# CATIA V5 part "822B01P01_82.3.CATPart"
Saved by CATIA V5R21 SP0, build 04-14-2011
Part number: 822B01P01_82.3
Bounding box of the stored display mesh (mm): x -17.1 to 17.1, y -41.15 to 41.15, z -11.6 to 4.4
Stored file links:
  C:\Users\ALI OZGUN\Desktop\alhan\TESLIMEDILEN3\822B01P01_82.3.CATPart
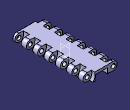
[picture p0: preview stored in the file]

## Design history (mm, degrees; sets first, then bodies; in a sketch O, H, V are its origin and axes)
Body1 (main body)
  Sketch1 on zx-plane, origin (0, 0, 0), H (-1, 0, 0), V (0, 0, 1)
    construction line L1 (-12.7, 0) -> (12.7, 0)
    point P1 (-12.7, 0)
    line L2 (-12.7, 4.4) -> (12.7, 4.4)
    line L3 (12.7, -4.4) -> (-12.7, -4.4)
    arc A1 centre (12.7, 0) radius 4.4 from (12.7, 4.4) to (12.7, -4.4) cw
    arc A2 centre (-12.7, 0) radius 4.4 from (-12.7, -4.4) to (-12.7, 4.4) cw
    distance L1 L2 = 4.4
    length L1 = 25.4
    distance P1 V = 12.7
    coincidence: P1 H
    horizontal: L1 H
    tangency: A1 L2, A2 L2, A1 L3, A2 L3
  Pad1: profile Sketch1, direction (0, 1, 0), length 76.2, mirrored extent
  Sketch2 on face of Pad1 from Sketch1.L2, origin (0, 0, 4.4), H (1, 0, 0), V (0, 1, 0)
    line L1 (-22.3127, -63.5) -> (-9.75, -63.5)
    line L2 (-9.75, -63.5) -> (-9.75, -70.6)
    line L3 (-9.75, -70.6) -> (-22.3127, -70.6)
    line L4 (-22.3127, -70.6) -> (-22.3127, -63.5)
    line L5 (24.6678, -76.95) -> (9.75, -76.95)
    line L6 (9.75, -76.95) -> (9.75, -69.85)
    line L7 (9.75, -69.85) -> (24.6678, -69.85)
    line L8 (24.6678, -69.85) -> (24.6678, -76.95)
    reference projected line E1 (-12.7, -76.2) -> (12.7, -76.2) from edge [start face of Pad1 | face of Pad1 from Sketch1.L2]
    reference projected line E2 (-12.7, -76.2) -> (12.7, -76.2) from edge [start face of Pad1 | face of Pad1 from Sketch1.L2]
    distance L3 E1 = 5.6
    length L4 = 7.1
    distance L7 L5 = 7.1
    distance L5 E2 = 0.75
    distance L2 L6 = 19.5
    distance L2 V = 9.75
    horizontal: L1 H, L3 H, L5 H, L7 H
    vertical: L2 V, L4 V, L6 V, L8 V
  Pocket1: profile Sketch2, direction (0, 0, -1), length 76.2
  RectPattern1: of Pocket1, direction 1 instances 12, spacing 12.7, along axis of face of Pad1 from Sketch1.A2
  Sketch3 on face of Pad1 from Sketch1.L3, origin (0, 0, -4.4), H (1, 0, 0), V (0, -1, 0)
    line L1 (-6.5, -54.6) -> (6.5, -54.6)
    line L2 (6.5, -54.6) -> (6.5, -73.7)
    line L3 (6.5, -73.7) -> (-6.5, -73.7)
    line L4 (-6.5, -73.7) -> (-6.5, -54.6)
    construction line L5 (-4.5, -51.1) -> (4.5, -51.1)
    point P5 (-4.5, -51.1)
    line L6 (-4.5, -49.6) -> (4.5, -49.6)
    line L7 (4.5, -52.6) -> (-4.5, -52.6)
    arc A1 centre (4.5, -51.1) radius 1.5 from (4.5, -49.6) to (4.5, -52.6) cw
    arc A2 centre (-4.5, -51.1) radius 1.5 from (-4.5, -52.6) to (-4.5, -49.6) cw
    reference projected line E1 (12.7, -76.2) -> (-12.7, -76.2) from edge [face of Pad1 from Sketch1.L3 | end face of Pad1]
    distance L5 L6 = 1.5
    distance L1 L3 = 19.1
    distance L4 L2 = 13
    distance L4 V = 6.5
    distance E1 L3 = 2.5
    distance P5 V = 4.5
    length L5 = 9
    distance L7 L1 = 2
    horizontal: L1 H, L3 H, L5 H
    vertical: L2 V, L4 V
    tangency: A1 L6, A2 L6, A1 L7, A2 L7
  Pocket2: profile Sketch3, direction (0, 0, 1), length 6
  RectPattern2: of Pocket2, direction 1 instances 6, spacing 25.8, along axis of face of Pad1 from Sketch1.A2 reversed
  Sketch4 on zx-plane, origin (0, 0, 0), H (-1, 0, 0), V (0, 0, 1)
    circle A1 centre (12.7, 0) radius 2.3
    point P1 (12.7, 0)
    circle A2 centre (-12.7, 0) radius 2.3
    point P2 (-12.7, 0)
    reference projected arc E1 centre (12.7, 0) radius 4.4 from (12.7, -4.4) to (12.7, 4.4) ccw from edge [face of RectPattern1 | face of Pad1 from Sketch1.A1]
    reference projected arc E2 centre (-12.7, 0) radius 4.4 from (-12.7, 4.4) to (-12.7, -4.4) ccw from edge [face of Pad1 from Sketch1.A2 | end face of Pad1]
    radius A1 = 2.3
    radius A2 = 2.3
    coincidence: P1 H, P2 H
    concentricity: P1 E1, A2 E2
  Pocket3: profile Sketch4, direction (0, -1, 0), length 97.8, mirrored extent
  Body2
    Solid1: linked copy from another document
    Symmetry1: Reference yz-plane, ToTransfor Solid1
    Translate1: ToTransfor Symmetry1, Direction edge [face of Pocket1 from Sketch2.L2 | face of Pad1 from Sketch1.L3], Length 6.35
    Body3
      Sketch5 on face of RectPattern1, origin (9.75, 0, 0), H (0, 1, 0), V (0, 0, 1)
      Pad2: profile Sketch5, direction (1, 0, 0), length 12
      Sketch6 on face of Pad2, origin (0, 69.85, 0), H (-1, 0, 0), V (0, 0, 1)
        point P2 (-21.75, 4.4)
        arc A1 centre (-16.5, 1.5645) radius 9 from (-9.7602, -4.4) to (-7.9583, 4.4) ccw
        point P8 (-21.75, 4.4)
        construction line L1 (-9.75, 4.4) -> (-21.75, 4.4)
        line L2 (-7.9583, 4.4) -> (-21.75, 4.4)
        line L3 (-9.7602, -4.4) -> (-21.75, -4.4)
        line L4 (-21.75, -4.4) -> (-21.75, 4.4)
        radius A1 = 9
        distance A1 V = 7.5
        coincidence: P2 P8
        fix: L2, L3
      Pad3: profile Sketch6, direction (0, 1, 0), up to face of Pad2
      RectPattern3: of the body so far, direction 1 instances 12, spacing 12.7, along edge [face of Pad3 | face of Pad3] reversed
    Add1: tool Body3
  Remove1: tool Body2
  RemoveFace1: RemoveFaces (face of RectPattern2; face of RectPattern2; face of RectPattern2; face of RectPattern2; face of RectPattern2)
  Sketch7 on face of Pad1 from Sketch1.L3, origin (0, 0, -4.4), H (1, 0, 0), V (0, -1, 0)
    line L1 (-6.5, 19.25) -> (6.5, 19.25)
    line L2 (6.5, 19.25) -> (6.5, -19.25)
    line L3 (6.5, -19.25) -> (-6.5, -19.25)
    line L4 (-6.5, -19.25) -> (-6.5, 19.25)
    point P5 (-6.5, -21.25)
    line L5 (-6.5, -21.25) -> (6.5, -21.25)
    line L6 (6.5, -21.25) -> (6.5, -47.75)
    line L7 (6.5, -47.75) -> (-6.5, -47.75)
    line L8 (-6.5, -47.75) -> (-6.5, -21.25)
    point P6 (6.5, -21.25)
    point P7 (6.5, -47.75)
    point P8 (-6.5, -47.75)
    point P9 (-6.5, 47.75)
    point P10 (6.5, 47.75)
    point P11 (6.5, 21.25)
    point P12 (-6.5, 21.25)
    line L9 (-6.5, 47.75) -> (-6.5, 21.25)
    line L10 (6.5, 47.75) -> (-6.5, 47.75)
    line L11 (6.5, 21.25) -> (6.5, 47.75)
    line L12 (-6.5, 21.25) -> (6.5, 21.25)
    reference projected line E1 (6.5, -73.7) -> (6.5, -54.6) from edge [face of Pad1 from Sketch1.L3 | face of Pocket2 from Sketch3.L2]
    reference projected line E2 (-6.5, -54.6) -> (-6.5, -73.7) from edge [face of Pad1 from Sketch1.L3 | face of Pocket2 from Sketch3.L4]
    distance L1 L3 = 38.5
    distance L3 H = 19.25
    distance L5 L3 = 2
    distance L7 L5 = 26.5
    horizontal: L1 H, L3 H, L5 H, L7 H
    vertical: L2 V, L4 V, L6 V, L8 V
    coincidence: P5 L4, P7 L2, L6 E1, L8 E2
    symmetry: P8 P9 H, P7 P10 H, P6 P11 H, P5 P12 H, L8 L9 H, L7 L10 H, L6 L11 H, L5 L12 H
  Pocket4: profile Sketch7, direction (0, 0, 1), length 6
  Sketch8 on end face of Pocket4, origin (0, 0, 1.6), H (1, 0, 0), V (0, -1, 0)
    projected line E1 (6.5, -21.25) -> (-6.5, -21.25) from edge [face of Pad1 from Sketch1.L3 | face of Pocket4 from Sketch7.L5]
    projected line E2 (5.6569, -21.25) -> (-5.6569, -21.25) from edge [face of Pad1 from Sketch1.L3 | face of Pocket4 from Sketch7.L5]
    arc A1 centre (0, -21.25) radius 6 from (-5.6569, -19.25) to (5.6569, -19.25) cw
    point P3 (0, -21.25)
    projected line E3 (-6.5, -19.25) -> (6.5, -19.25) from edge [face of Pad1 from Sketch1.L3 | face of Pocket4 from Sketch7.L3]
    projected line E4 (-5.6569, -19.25) -> (5.6569, -19.25) from edge [face of Pad1 from Sketch1.L3 | face of Pocket4 from Sketch7.L3]
    point P6 (5.6569, -19.25)
    point P7 (-5.6569, -19.25)
    line L1 (5.6569, -19.25) -> (5.6569, -21.25)
    point P9 (-5.6569, -19.25)
    line L2 (-5.6569, -19.25) -> (-5.6569, -21.25)
    radius A1 = 6
    coincidence: P3 E1, P3 V, P7 P9
    vertical: L1 V
    symmetry: P6 P9 V, L1 L2 V
  Pad4: profile Sketch8, direction (0, 0, -1), length 13.2
  TritangentFillet1: Face1 face of Pad4, Face2 face of Pad4 from Sketch8.A1, RemoveFace face of Pad4 from Sketch8.L1
  TritangentFillet2: Face1 face of Pad4, Face2 face of Pad4 from Sketch8.A1, RemoveFace face of Pad4 from Sketch8.L2
  Mirror1: of Pad4, Sketch8, about zx-plane
  TritangentFillet3: Face1 face of Mirror1, Face2 face of Mirror1, RemoveFace face of Mirror1
  TritangentFillet4: Face1 face of Mirror1, Face2 face of Mirror1, RemoveFace face of Mirror1
  Sketch9 on end face of Pad4, origin (0, 0, -11.6), H (1, 0, 0), V (0, -1, 0)
    arc A1 centre (0, 21.2499) radius 3.9999 from (3.4641, 19.25) to (-3.4641, 19.25) cw
    line L1 (3.4641, 19.25) -> (-3.4641, 19.25)
  Pocket5: profile Sketch9, direction (0, 0, 1), up to end face of Pocket4
  Fillet1: radius 0.5, on edge [face of Pocket5 | face of Pocket5] (x2); edge [face of Pocket5 from Sketch9.A1 | face of Pocket5 from Sketch9.L1]; edge [face of Pocket5 from Sketch9.L1 | face of Pocket5 from Sketch9.A1]
  Sketch10 on face of Pad1 from Sketch1.L3, origin (0, 0, -4.4), H (1, 0, 0), V (0, -1, 0)
    line L1 (27.295, 41.15) -> (27.295, -41.15)
    line L2 (27.295, -41.15) -> (-27.295, -41.15)
    line L3 (-27.295, -41.15) -> (-27.295, 41.15)
    line L4 (-27.295, 41.15) -> (27.295, 41.15)
    length L1 = 82.3
    vertical: L1 V, L3 V
    horizontal: L2 H, L4 H
    equidistance: L1 L3 O, L2 L4 O
  Pocket6: profile Sketch10, direction (0, 0, 1), length 13.2, outer side
Body4
  Solid2: linked copy from another document
  Translate2: ToTransfor Solid2, Direction yz-plane, Length 25.4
